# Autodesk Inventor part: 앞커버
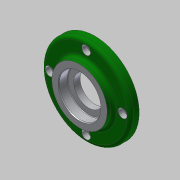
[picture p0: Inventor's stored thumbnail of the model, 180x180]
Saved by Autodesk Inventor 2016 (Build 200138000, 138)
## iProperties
Created: 2019-01
Part Number: 앞커버
Material: 알루미늄 6061
Document SubType Name: Modeling
Designer: mduedu
Density: 1 g/cm^3
Appearance: 알루미늄 - 평지
Author: mduedu
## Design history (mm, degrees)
sketch "스케치1"
  geometry: L1 (0, 0)-(6, 0); L2 (6, 0)-(6, 25); L3 (6, 25)-(0, 25); L4 (0, 25)-(0, 0); L5 (6, 0)-(14, 0); L6 (14, 0)-(14, 40); L7 (14, 40)-(6, 40); L8 (6, 40)-(6, 0); L9 (14, 0)-(19, 0); L10 (19, 0)-(19, 26); L11 (19, 26)-(14, 26); L12 (14, 26)-(14, 0)
  constraints: 24 end point, 6 parallel, 3 horizontal, 3 perpendicular
  dimensions: "d6" = 80 diameter of L7 L5; "d8" = 50 diameter of L3 L1; "d9" = 52 diameter of L11 L9; "d10" = 5 distance of L10.end L11.end; "d11" = 6 distance of L2.end L3.end; "d12" = 19 distance between parallel lines of L4 L10; "d13" = 8 distance of L6.end L7.end (derived)
revolve "회전1" sketch "스케치1" stored, may be unused: angle "d5" = 90 deg
sketch "스케치2"
  geometry: C1 r 13.5 at (0, 0); 1 further point
  constraints: 1 centre point, 1 coincident
  dimensions: "d14" = 27 diameter of C1
extrude "돌출1" cut sketch "스케치2" stored distance "d15" = 10; taper "d16" = 0 deg
sketch "스케치3" dims "d17" = 66
  geometry: 6 further points
  constraints: 2 vertical alignment, 1 coincident, 7 other
  dimensions: "d20" = 360 deg dimension on point (0, 0) point (0, 33) (derived)
sketch "스케치4"
  geometry: 4 further points
  constraints: 4 other
hole "구멍1" sketch "스케치4" at (-33, 0), (0, -33), (33, 0), (0, 33) diameter "d22" = 4.5; stored, may be unused: countersink angle "d26" = 90 deg, drill point angle "d28" = 0 deg; dims "d23" = 6, "d24" = 8, "d25" = 4.6, "d27" = 8
fillet "모깎기1" dims "d29" = 3
sketch "스케치5"
  geometry: C1 r 19 at (0, 0); 1 further point
  constraints: 1 centre point, 1 coincident
  dimensions: "d30" = 38 diameter of C1
extrude "돌출2" cut sketch "스케치5" distance "d31" = 8.3; taper "d32" = 0 deg
fillet "모깎기2" dims "d33" = 3
chamfer "모따기1" distance "d34" = 0.8; stored, may be unused: second distance "d35" = 2, angle "d36" = 30 deg
fillet "모깎기3" dims "d37" = 0.5
sketch "스케치6"
  geometry: C1 r 22 at (0, 0); 1 further point
  constraints: 1 centre point, 1 coincident
  dimensions: "d38" = 44 diameter of C1
extrude "돌출3" cut sketch "스케치6" distance "d39" = 5; taper "d40" = 0 deg
fillet "모깎기4" dims "d41" = 3
chamfer "모따기2" distance "d42" = 1; stored, may be unused: second distance "d43" = 2, angle "d44" = 30 deg
node "솔리드1"
